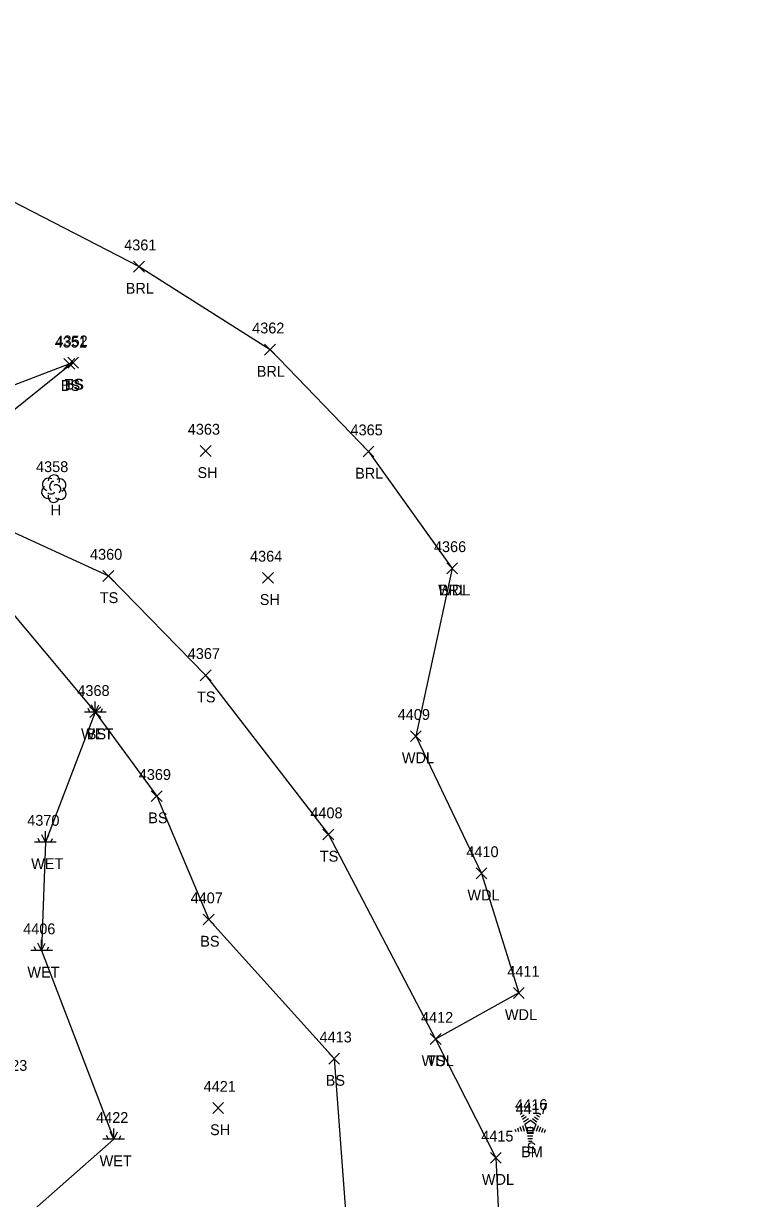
# Model space of a CAD drawing. Extents: x 1505656 to 1508446, y 700805 to 703031.
# Drawn here: x 1507075.1 to 1507206.6, y 701922.6 to 702139.5 of the extents above; entities that cross this region are included whole.
import ezdxf

# ---------------------------------------------------------------- set-up
doc = ezdxf.new("R2010")
doc.units = 0
for name, color, linetype in [('C_A', 7, 'Continuous'), ('C_I', 7, 'Continuous'), ('CPBM', 7, 'Continuous'), ('L_A', 7, 'Continuous'), ('L_I', 7, 'Continuous'), ('L_TIC', 7, 'Continuous'), ('LABL', 7, 'Continuous'), ('LAWA', 7, 'Continuous'), ('LELB', 7, 'Continuous'), ('LTC', 7, 'Continuous'), ('LTD', 7, 'Continuous'), ('LWET', 7, 'Continuous')]:
    doc.layers.add(name, color=color, linetype=linetype)

msp = doc.modelspace()

# ---------------------------------------------------------------- linework, layer by layer
at = {"layer": 'CPBM'}
for p, q in [((1507168.17, 701934.67), (1507168.17, 701935.67)), ((1507168.17, 701935.67), (1507169.17, 701935.67)), ((1507169.17, 701934.67), (1507168.17, 701934.67)), ((1507168.67, 701935.17), (1507168.67, 701935.17)), ((1507168.67, 701935.17), (1507168.67, 701935.17)), ((1507169.17, 701935.67), (1507169.17, 701934.67))]:
    msp.add_line(p, q, dxfattribs=at)
at = {"layer": 'L_TIC'}
for points in [[(1507095.41, 702093.62), (1507097.41, 702095.62)], [(1507097.41, 702093.62), (1507095.41, 702095.62)], [(1507119.62, 702078.29), (1507121.62, 702080.29)], [(1507121.62, 702078.29), (1507119.62, 702080.29)], [(1507082.53, 702075.67), (1507084.53, 702077.67)], [(1507084.53, 702075.67), (1507082.53, 702077.67)], [(1507083.24, 702075.9), (1507085.24, 702077.9)], [(1507085.24, 702075.9), (1507083.24, 702077.9)], [(1507083.24, 702075.9), (1507085.24, 702077.9)], [(1507085.24, 702075.9), (1507083.24, 702077.9)], [(1507107.72, 702059.59), (1507109.72, 702061.59)], [(1507109.72, 702059.59), (1507107.72, 702061.59)], [(1507137.79, 702059.47), (1507139.79, 702061.47)], [(1507139.79, 702059.47), (1507137.79, 702061.47)], [(1507089.75, 702036.5), (1507091.75, 702038.5)], [(1507091.75, 702036.5), (1507089.75, 702038.5)], [(1507153.26, 702037.91), (1507155.26, 702039.91)], [(1507155.26, 702037.91), (1507153.26, 702039.91)], [(1507153.26, 702037.91), (1507155.26, 702039.91)], [(1507155.26, 702037.91), (1507153.26, 702039.91)], [(1507119.23, 702036.15), (1507121.23, 702038.15)], [(1507121.23, 702036.15), (1507119.23, 702038.15)], [(1507107.72, 702018.17), (1507109.72, 702020.17)], [(1507109.72, 702018.17), (1507107.72, 702020.17)], [(1507087.33, 702011.34), (1507089.33, 702013.34)], [(1507089.33, 702011.34), (1507087.33, 702013.34)], [(1507146.54, 702006.93), (1507148.54, 702008.93)], [(1507148.54, 702006.93), (1507146.54, 702008.93)], [(1507098.68, 701995.84), (1507100.68, 701997.84)], [(1507100.68, 701995.84), (1507098.68, 701997.84)], [(1507130.39, 701988.76), (1507132.39, 701990.76)], [(1507132.39, 701988.76), (1507130.39, 701990.76)], [(1507158.66, 701981.59), (1507160.66, 701983.59)], [(1507160.66, 701981.59), (1507158.66, 701983.59)], [(1507108.28, 701973.06), (1507110.28, 701975.06)], [(1507110.28, 701973.06), (1507108.28, 701975.06)], [(1507165.57, 701959.51), (1507167.57, 701961.51)], [(1507167.57, 701959.51), (1507165.57, 701961.51)], [(1507150.2, 701951), (1507152.2, 701953)], [(1507152.2, 701951), (1507150.2, 701953)], [(1507150.2, 701951), (1507152.2, 701953)], [(1507152.2, 701951), (1507150.2, 701953)], [(1507131.45, 701947.38), (1507133.45, 701949.38)], [(1507133.45, 701947.38), (1507131.45, 701949.38)], [(1507110.04, 701938.26), (1507112.04, 701940.26)], [(1507112.04, 701938.26), (1507110.04, 701940.26)], [(1507161.32, 701929.08), (1507163.32, 701931.08)], [(1507163.32, 701929.08), (1507161.32, 701931.08)]]:
    msp.add_lwpolyline(points, dxfattribs=at)
at = {"layer": 'LABL'}
msp.add_lwpolyline([(1507052.35, 702139.51), (1507030.38, 702125.98), (1507008.56, 702109.93), (1506976.55, 702082.74), (1506991.06, 702056.7), (1507008.55, 702068.3), (1507027.17, 702084.23), (1507053.07, 702102.48), (1507064.87, 702110.91), (1507096.41, 702094.62), (1507120.62, 702079.29), (1507138.79, 702060.47), (1507154.26, 702038.91)], dxfattribs=at)
at = {"layer": 'LAWA'}
msp.add_lwpolyline([(1507154.26, 702038.91), (1507147.54, 702007.93), (1507159.66, 701982.59), (1507166.57, 701960.51), (1507151.2, 701952), (1507162.32, 701930.08), (1507163.96, 701895.29), (1507132.1, 701887.48), (1507137.81, 701863.42), (1507170.65, 701859.1), (1507197.18, 701858.37), (1507206.6, 701829.57)], dxfattribs=at)
at = {"layer": 'LELB'}
for points in [[(1507020.31, 702047.85), (1507041.33, 702060.54), (1507083.53, 702076.67), (1507084.24, 702076.9)], [(1507084.24, 702076.9), (1507063.73, 702060.5), (1507060.51, 702049.63), (1507070.34, 702046.86), (1507090.75, 702037.5), (1507108.72, 702019.17), (1507131.39, 701989.76), (1507151.2, 701952)], [(1507088.33, 702012.34), (1507099.68, 701996.84), (1507109.28, 701974.06), (1507132.45, 701948.38), (1507134.97, 701914.52), (1507115.44, 701901.79), (1507092.5, 701907.07), (1507054.97, 701897.37)]]:
    msp.add_lwpolyline(points, dxfattribs=at)
at = {"layer": 'LTC'}
for p, q in [((1507166.83, 701938.11), (1507167.18, 701938.37)), ((1507167.04, 701937.65), (1507167.57, 701938.03)), ((1507167.25, 701937.18), (1507167.95, 701937.69)), ((1507167.46, 701936.72), (1507168.34, 701937.35)), ((1507167.68, 701936.26), (1507168.7, 701937)), ((1507167.68, 701936.26), (1507168.07, 701935.07)), ((1507168.7, 701937), (1507169.69, 701936.27)), ((1507169.12, 701937.31), (1507169.92, 701936.72)), ((1507169.69, 701936.27), (1507169.3, 701935.07)), ((1507169.49, 701937.66), (1507170.17, 701937.16)), ((1507169.86, 701938), (1507170.41, 701937.61)), ((1507170.23, 701938.35), (1507170.65, 701938.05)), ((1507165.86, 701935.39), (1507166.01, 701934.92)), ((1507166.32, 701935.61), (1507166.53, 701934.96)), ((1507166.77, 701935.83), (1507167.04, 701934.99)), ((1507167.23, 701936.04), (1507167.56, 701935.02)), ((1507169.3, 701935.07), (1507168.07, 701935.07)), ((1507169.26, 701934.57), (1507168.12, 701934.57)), ((1507170.13, 701936), (1507169.79, 701934.96)), ((1507170.57, 701935.75), (1507170.29, 701934.86)), ((1507171.02, 701935.5), (1507170.78, 701934.77)), ((1507171.46, 701935.25), (1507171.28, 701934.67)), ((1507169.18, 701934.07), (1507168.19, 701934.07)), ((1507169.1, 701933.57), (1507168.26, 701933.57)), ((1507169.01, 701933.07), (1507168.34, 701933.07))]:
    msp.add_line(p, q, dxfattribs=at)
at = {"layer": 'LTD'}
msp.add_line((1507080.65, 702053.68), (1507080.65, 702053.68), dxfattribs=at)
msp.add_line((1507080.65, 702053.68), (1507080.65, 702053.68), dxfattribs=at)
msp.add_arc((1507080.69, 702055.11), 1.05, 335.5272, 180.9563, dxfattribs=at)
for centre, major_axis, ratio, start_param, end_param in [((1507079.85, 702054.35), (1.21, -0.51), 0.895232, 1.570796, 4.712389), ((1507081.69, 702054.26), (-1.14, -0.48), 0.949671, 1.570796, 4.712389), ((1507079.56, 702052.97), (0.58, -1.04), 0.959034, 3.141593, 6.283185), ((1507080.44, 702054.14), (-0.208, -0.792), 0.645439, 3.141593, 6.283185), ((1507081.15, 702053.51), (-0.5, 0.667), 0.989748, 3.141593, 6.283185), ((1507081.65, 702052.85), (-1.09, 0.79), 0.841452, 1.570796, 4.712389), ((1507080.65, 702052.18), (0.26, 1.06), 0.942809, 1.570796, 4.712389), ((1507080.19, 702052.93), (-0.625, -0.083), 0.423636, 0, 3.141593)]:
    msp.add_ellipse(centre, major_axis=major_axis, ratio=ratio, start_param=start_param, end_param=end_param, dxfattribs=at)
at = {"layer": 'LWET'}
for p, q in [((1507090.33, 702012.34), (1507086.33, 702012.34)), ((1507087.33, 702012.34), (1507087, 702013.01)), ((1507088.33, 702012.34), (1507087.66, 702013.68)), ((1507088.33, 702012.34), (1507088.33, 702014.34)), ((1507088.33, 702012.34), (1507089, 702013.68)), ((1507089.33, 702012.34), (1507089.66, 702013.01)), ((1507081.11, 701988.38), (1507077.11, 701988.38)), ((1507078.11, 701988.38), (1507077.77, 701989.05)), ((1507079.11, 701988.38), (1507078.44, 701989.71)), ((1507079.11, 701988.38), (1507079.11, 701990.38)), ((1507079.11, 701988.38), (1507079.77, 701989.71)), ((1507080.11, 701988.38), (1507080.44, 701989.05)), ((1507077.41, 701968.35), (1507077.07, 701969.02)), ((1507078.41, 701968.35), (1507077.74, 701969.69)), ((1507078.41, 701968.35), (1507078.41, 701970.35)), ((1507078.41, 701968.35), (1507079.07, 701969.69)), ((1507079.41, 701968.35), (1507079.74, 701969.02)), ((1507080.41, 701968.35), (1507076.41, 701968.35)), ((1507090.75, 701933.51), (1507090.42, 701934.18)), ((1507091.75, 701933.51), (1507091.08, 701934.85)), ((1507091.75, 701933.51), (1507091.75, 701935.51)), ((1507091.75, 701933.51), (1507092.42, 701934.85)), ((1507092.75, 701933.51), (1507093.08, 701934.18)), ((1507093.75, 701933.51), (1507089.75, 701933.51))]:
    msp.add_line(p, q, dxfattribs=at)
msp.add_lwpolyline([(1507008.55, 702068.3), (1507020.31, 702047.85), (1507056.72, 702049.31), (1507069.4, 702034.86), (1507088.33, 702012.34), (1507079.11, 701988.38), (1507078.41, 701968.35), (1507091.75, 701933.51), (1507071.91, 701916.06), (1507054.97, 701897.37), (1507040.22, 701883.4), (1507020.93, 701866.15), (1507002.45, 701844.9), (1506990.1, 701859.78), (1506976.94, 701877.74), (1506962.87, 701900.93), (1506956.96, 701914.6), (1506952.95, 701929.12), (1506947.58, 701946.18)], dxfattribs=at)

# ---------------------------------------------------------------- texts
at = {"layer": 'C_A'}
msp.add_text('BM', height=2, dxfattribs=at).set_placement((1507166.98, 701930.17))
at = {"layer": 'C_I'}
msp.add_text('4417', height=2, dxfattribs=at).set_placement((1507165.98, 701938.17))
at = {"layer": 'L_A'}
for s, p in [('BRL', (1507093.95, 702089.62)), ('BRL', (1507118.16, 702074.29)), ('BS', (1507081.97, 702071.67)), ('TS', (1507082.65, 702071.9)), ('BS', (1507082.68, 702071.9)), ('SH', (1507107.21, 702055.59)), ('BRL', (1507136.33, 702055.47)), ('H', (1507080.08, 702048.68)), ('TS', (1507089.16, 702032.5)), ('SH', (1507118.71, 702032.15)), ('WDL', (1507151.67, 702033.91)), ('BRL', (1507151.8, 702033.91)), ('TS', (1507107.13, 702014.17)), ('WET', (1507085.71, 702007.34)), ('BS', (1507086.77, 702007.34)), ('WDL', (1507144.96, 702002.93)), ('BS', (1507098.12, 701991.84)), ('TS', (1507129.8, 701984.76)), ('WET', (1507076.48, 701983.38)), ('WDL', (1507157.07, 701977.59)), ('BS', (1507107.72, 701969.06)), ('WET', (1507075.79, 701963.35)), ('WDL', (1507163.99, 701955.51)), ('WDL', (1507148.61, 701947)), ('TS', (1507149.61, 701947)), ('BS', (1507130.89, 701943.38)), ('SH', (1507109.53, 701934.26)), ('S', (1507168.02, 701930.9)), ('WET', (1507089.13, 701928.51)), ('WDL', (1507159.74, 701925.08))]:
    msp.add_text(s, height=2, dxfattribs=at).set_placement(p)
at = {"layer": 'L_I'}
for s, p in [('4361', (1507093.67, 702097.62)), ('4362', (1507117.31, 702082.29)), ('4351', (1507080.83, 702079.67)), ('4352', (1507080.98, 702079.9)), ('4352', (1507080.98, 702079.9)), ('4363', (1507105.42, 702063.59)), ('4365', (1507135.48, 702063.47)), ('4358', (1507077.39, 702056.68)), ('4366', (1507150.89, 702041.91)), ('4366', (1507150.89, 702041.91)), ('4360', (1507087.36, 702040.5)), ('4364', (1507116.92, 702040.15)), ('4367', (1507105.41, 702022.17)), ('4368', (1507085.02, 702015.34)), ('4368', (1507085.02, 702015.34)), ('4409', (1507144.2, 702010.93)), ('4369', (1507096.36, 701999.84)), ('4370', (1507075.76, 701991.38)), ('4408', (1507128.06, 701992.76)), ('4410', (1507156.88, 701985.59)), ('4407', (1507105.94, 701977.06)), ('4406', (1507075.01, 701971.35)), ('4411', (1507164.45, 701963.51)), ('4412', (1507148.5, 701955)), ('4412', (1507148.5, 701955)), ('4413', (1507129.76, 701951.38)), ('4423', (1507069.82, 701946.13)), ('4421', (1507108.35, 701942.26)), ('4416', (1507165.89, 701938.9)), ('4422', (1507088.49, 701936.51)), ('4415', (1507159.63, 701933.08))]:
    msp.add_text(s, height=2, dxfattribs=at).set_placement(p)
at = {"layer": 'LTC'}
msp.add_text('.', height=1.04, rotation=270, dxfattribs=at).set_placement((1507168.58, 701936.01))

doc.saveas('drawing.dxf')
